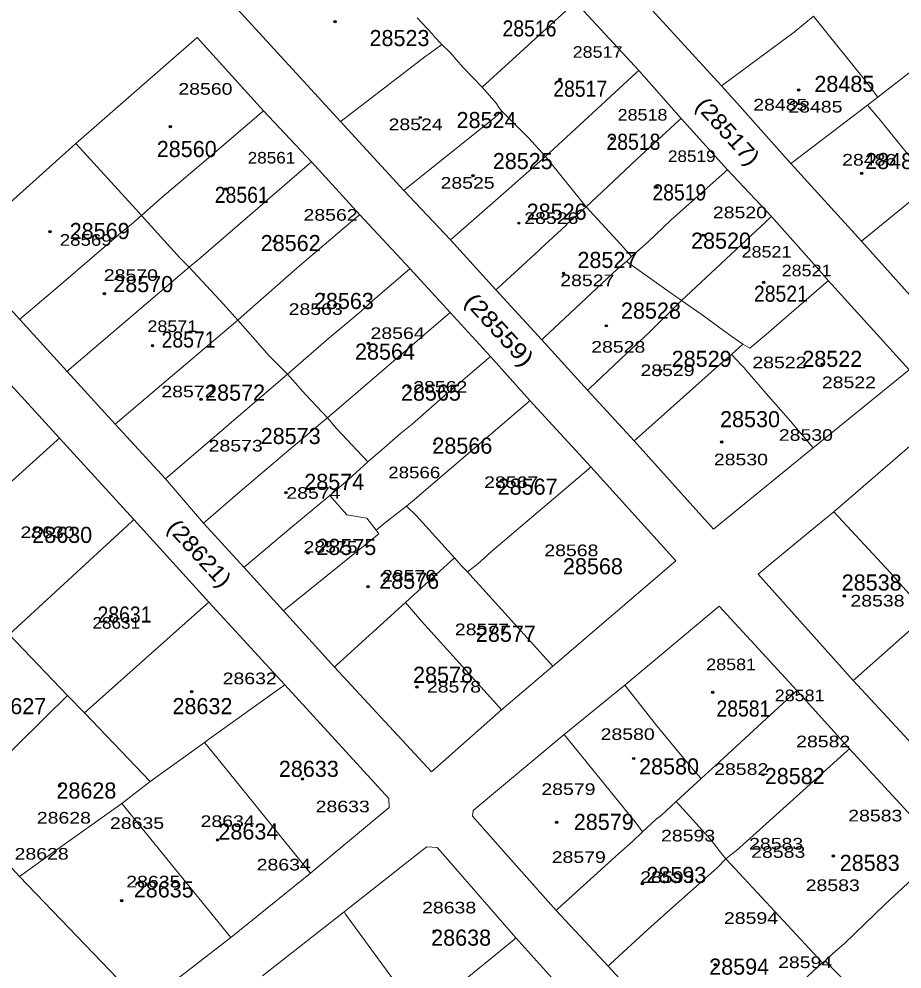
# Model space of a CAD drawing. Extents: x 650553 to 652508, y 239277 to 241647.
# Drawn here: x 651208.2 to 651405.4, y 240724.2 to 240936.5 of the extents above; entities that cross this region are included whole.
import ezdxf

# ---------------------------------------------------------------- set-up
doc = ezdxf.new("R2010")
doc.units = 0
doc.header["$PDMODE"] = 32
doc.header["$PDSIZE"] = 0.5
for name, color, linetype in [('19', 7, 'Continuous'), ('20', 7, 'Continuous'), ('6', 7, 'Continuous')]:
    doc.layers.add(name, color=color, linetype=linetype)
doc.layers.add('3', color=7, linetype='Continuous', lineweight=13)
doc.layers.add('5', color=7, linetype='Continuous', lineweight=13)

msp = doc.modelspace()

# ---------------------------------------------------------------- linework, layer by layer
at = {"layer": '3'}
msp.add_line((651343.46, 240787.65), (651329.9, 240776.61), dxfattribs=at)
for points in [[(651277, 240958.16), (651298.11, 240977.12), (651318.05, 240955.47), (651332.44, 240940.26), (651346.55, 240924.99), (651356.03, 240914.24), (651366.39, 240902.79)], [(651380.56, 240904.16), (651375, 240910.37), (651369.11, 240916.96), (651365.03, 240921.5), (651349.46, 240938.51), (651334.15, 240954.49), (651318.32, 240971.34)], [(651279.96, 240913.54), (651256.05, 240939.64), (651277, 240958.16)], [(651220.87, 240908.63), (651247.95, 240932.31), (651262.76, 240915.94), (651273.46, 240904.58), (651284.26, 240892.74), (651295.51, 240880.67), (651304.42, 240870.91), (651313.42, 240861.04), (651322.27, 240851.23), (651335.9, 240836.4)], [(651385.53, 240840.68), (651375, 240832.09), (651363.23, 240822.48), (651345.55, 240842.23), (651335.12, 240853.52), (651324.91, 240864.81), (651314.68, 240875.96), (651304.55, 240887.13), (651294.1, 240898.18), (651279.96, 240913.54)], [(651208.31, 240869.33), (651194.27, 240884.81), (651220.87, 240908.63)], [(651366.39, 240902.79), (651375, 240893.59), (651376.18, 240892.33)], [(651430.38, 240877.39), (651415.54, 240865.35), (651396.3, 240886.8), (651380.56, 240904.16)], [(651376.18, 240892.33), (651386.915, 240880.255), (651388.92, 240878)], [(651165.74, 240859.56), (651185.75, 240877.17), (651202.38, 240859), (651217.18, 240842.81), (651233.79, 240824.62), (651250.56, 240806.18), (651267.52, 240787.73)], [(651388.92, 240878), (651406.98, 240858.1), (651385.53, 240840.68)], [(651315.92, 240782.11), (651300.27, 240768.31), (651278.58, 240791.67), (651267.23, 240804.28), (651258.4, 240813.97), (651249.36, 240823.83), (651240.86, 240833.76), (651229.66, 240845.97), (651218.88, 240857.7), (651208.31, 240869.33)], [(651390.1, 240826.37), (651415.79, 240848.55), (651436.19, 240825.84)], [(651335.9, 240836.4), (651354.84, 240815.44), (651327.38, 240791.89), (651315.92, 240782.11)], [(651375, 240813.9), (651386.148, 240823.106), (651390.1, 240826.37)], [(651375, 240813.9), (651373.2, 240812.42), (651375, 240810.41)], [(651208.28, 240744.9), (651203.48, 240750), (651193.67, 240760.43), (651177.86, 240776.79), (651162.01, 240793.16), (651146.4, 240809.27)], [(651375, 240810.41), (651394.45, 240788.7), (651405.88, 240776.28), (651417.31, 240763.69), (651428.702, 240751.214)], [(651375, 240793.89), (651364.54, 240805.26), (651343.46, 240787.65)], [(651375, 240793.89), (651381.88, 240786.41), (651393.61, 240773.4), (651414.55, 240750.7), (651415.19, 240750)], [(651267.52, 240787.73), (651290.76, 240762.29), (651290.81, 240760.29), (651278.45, 240750), (651273.22, 240745.65), (651255.48, 240731.26)], [(651329.9, 240776.61), (651309.57, 240759.62), (651309.42, 240758.34), (651316.83, 240750)], [(651262.55, 240722.73), (651280.74, 240736.96), (651297.28, 240750)], [(651302.75, 240750), (651301.54, 240751.39), (651299.25, 240751.55), (651297.28, 240750)], [(651302.75, 240750), (651319.13, 240731.15), (651331.81, 240717.05), (651347.16, 240700.26), (651362.6, 240683.5), (651375, 240670.03)], [(651369.97, 240691.81), (651368.88, 240693.01), (651361.16, 240701.58), (651339.76, 240724.88), (651328.09, 240737.32), (651316.83, 240750)], [(651255.48, 240731.26), (651238.03, 240717.81), (651233.93, 240718.13), (651208.28, 240744.9)]]:
    msp.add_lwpolyline(points, dxfattribs=at)
at = {"layer": '5'}
for p, q in [((651325.71, 240905.76), (651313.89, 240895.31)), ((651396.3, 240886.8), (651412.1, 240899.78)), ((651356.14, 240873.55), (651348.86, 240866.39)), ((651257.05, 240869.2), (651238.03, 240853.13)), ((651277.58, 240830.02), (651281.34, 240825.68)), ((651402.77, 240812.7), (651390.1, 240826.37)), ((651219, 240785.29), (651205.99, 240798.98)), ((651237.46, 240766.15), (651222.76, 240781.42)), ((651249.59, 240774.83), (651252.315, 240771.465)), ((651255.48, 240731.26), (651240.23, 240750)), ((651365.99, 240748.81), (651365.07, 240750)), ((651365.99, 240748.81), (651375, 240739.13)), ((651387.627, 240725.567), (651375, 240739.13))]:
    msp.add_line(p, q, dxfattribs=at)
for points in [[(651397.68, 240917.22), (651399.98, 240918.99), (651432.63, 240944.47)], [(651311.58, 240921.24), (651331.94, 240939.804), (651332.44, 240940.26)], [(651297.06, 240936.72), (651300.53, 240933.07), (651300.98, 240932.48), (651302.55, 240930.74), (651299.76, 240928.68), (651299.1, 240928.23)], [(651399.98, 240918.99), (651396.6, 240923.39), (651389.13, 240932.6), (651385.61, 240937.08), (651381.24, 240933.55), (651375, 240928.91)], [(651302.55, 240930.74), (651304.43, 240928.96), (651307.24, 240925.67), (651311.58, 240921.24)], [(651299.1, 240928.23), (651280.46, 240913.924), (651279.96, 240913.54)], [(651365.03, 240921.5), (651365.53, 240921.872), (651375, 240928.91)], [(651332.39, 240911.85), (651346.05, 240924.526), (651346.55, 240924.99)], [(651311.58, 240921.24), (651314.78, 240917.57), (651315.28, 240916.72), (651315.97, 240915.84), (651314.43, 240914.49)], [(651397.68, 240917.22), (651381.06, 240904.541), (651380.56, 240904.16)], [(651430.38, 240877.39), (651429.968, 240877.89), (651422.71, 240886.7), (651415.97, 240895.15), (651412.1, 240899.78), (651408.2, 240904.34), (651401.46, 240912.71), (651400.99, 240913.24), (651397.68, 240917.22)], [(651251.39, 240906.19), (651262.26, 240915.511), (651262.76, 240915.94)], [(651315.97, 240915.84), (651321.95, 240909.9), (651325.71, 240905.76), (651332.39, 240911.85)], [(651314.43, 240914.49), (651294.6, 240898.581), (651294.1, 240898.18)], [(651346.1, 240905.15), (651355.53, 240913.782), (651356.03, 240914.24)], [(651220.87, 240908.63), (651234.21, 240894), (651235.5, 240892.55), (651240.14, 240896.69), (651251.39, 240906.19)], [(651248.75, 240883.19), (651272.96, 240904.147), (651273.46, 240904.58)], [(651325.71, 240905.76), (651334.8, 240894.52), (651340.84, 240900.2), (651346.1, 240905.15)], [(651353.74, 240891.54), (651365.89, 240902.345), (651366.39, 240902.79)], [(651313.89, 240895.31), (651305.05, 240887.568), (651304.55, 240887.13)], [(651334.8, 240894.52), (651330.55, 240890.67), (651330.25, 240890.32), (651324.72, 240885.23), (651324.28, 240884.77)], [(651334.8, 240894.52), (651342.56, 240886.06), (651344.92, 240883.42), (651348.66, 240886.7), (651353.74, 240891.54)], [(651235.5, 240892.55), (651233.21, 240890.57), (651231.41, 240889.12), (651217.57, 240877.22)], [(651235.5, 240892.55), (651244.06, 240883.12), (651246.19, 240880.99), (651248.75, 240883.19)], [(651271.81, 240882.22), (651283.76, 240892.318), (651284.26, 240892.74)], [(651376.18, 240892.33), (651375.68, 240891.86), (651375, 240891.22)], [(651343.8, 240882.32), (651352.31, 240876.24), (651356.14, 240873.55), (651357.08, 240874.5), (651375, 240891.22)], [(651324.28, 240884.77), (651315.18, 240876.419), (651314.68, 240875.96)], [(651344.92, 240883.42), (651343.8, 240882.32), (651341.75, 240880.57)], [(651246.19, 240880.99), (651253.84, 240872.72), (651257.05, 240869.2), (651259.08, 240871.04), (651270.8, 240881.3), (651271.81, 240882.22)], [(651246.19, 240880.99), (651219.38, 240858.126), (651218.88, 240857.7)], [(651287.09, 240873.47), (651295.01, 240880.242), (651295.51, 240880.67)], [(651341.75, 240880.57), (651325.41, 240865.278), (651324.91, 240864.81)], [(651217.57, 240877.22), (651208.81, 240869.756), (651208.31, 240869.33)], [(651388.92, 240878), (651388.42, 240877.567), (651376.226, 240867.009), (651375, 240865.98)], [(651257.05, 240869.2), (651260.92, 240864.79), (651263.92, 240861.32), (651268.1, 240857.11), (651269.87, 240858.68), (651277.32, 240865.19), (651281.79, 240868.92), (651284.54, 240871.22), (651287.09, 240873.47)], [(651356.14, 240873.55), (651360.72, 240870.34), (651366.62, 240866.09), (651369.84, 240863.85), (651371.38, 240862.94), (651375, 240865.98)], [(651277.05, 240847.33), (651303.92, 240870.479), (651304.42, 240870.91)], [(651345.01, 240862.86), (651346.53, 240864.21), (651348.86, 240866.39)], [(651345.01, 240862.86), (651335.62, 240853.992), (651335.12, 240853.52)], [(651369.84, 240863.85), (651367.26, 240861.49), (651364.8, 240859.39)], [(651306.8, 240855.38), (651312.92, 240860.613), (651313.42, 240861.04)], [(651367.26, 240861.49), (651369.56, 240859.06), (651370.01, 240858.6)], [(651364.8, 240859.39), (651346.05, 240842.676), (651345.55, 240842.23)], [(651370.01, 240858.6), (651375, 240852.77), (651379.961, 240847.191), (651385.53, 240840.68)], [(651268.1, 240857.11), (651241.36, 240834.189), (651240.86, 240833.76)], [(651268.1, 240857.11), (651272.11, 240852.59), (651277.05, 240847.33)], [(651277.05, 240847.33), (651279, 240845.08), (651286.06, 240837.5), (651290.27, 240841.21), (651290.98, 240841.77), (651293.39, 240843.88), (651295.96, 240845.98), (651302.23, 240851.45), (651306.8, 240855.38)], [(651238.03, 240853.13), (651230.16, 240846.398), (651229.66, 240845.97)], [(651296.47, 240829.13), (651321.77, 240850.802), (651322.27, 240851.23)], [(651277.05, 240847.33), (651275.84, 240846.37), (651267.49, 240839.43), (651264.94, 240837.16), (651262.53, 240835.14), (651257.54, 240830.88)], [(651188.61, 240817.03), (651216.68, 240842.359), (651217.18, 240842.81)], [(651286.06, 240837.5), (651281.64, 240833.54), (651277.58, 240830.02), (651268.42, 240822.41)], [(651313.77, 240817.56), (651335.4, 240835.974), (651335.9, 240836.4)], [(651257.54, 240830.88), (651249.86, 240824.261), (651249.36, 240823.83)], [(651287.93, 240822.23), (651290.05, 240824.05), (651294.68, 240827.64), (651296.47, 240829.13)], [(651294.68, 240827.64), (651296.93, 240825.46), (651305.39, 240816.07), (651299.73, 240810.97), (651294.44, 240806.14)], [(651205.99, 240798.98), (651233.29, 240824.159), (651233.79, 240824.62)], [(651281.34, 240825.68), (651285.87, 240824.95), (651287.93, 240822.23)], [(651268.42, 240822.41), (651258.9, 240814.391), (651258.4, 240813.97)], [(651287.93, 240822.23), (651288.48, 240821.42), (651267.73, 240804.683), (651267.23, 240804.28)], [(651308.35, 240812.97), (651309.86, 240814.18), (651311.24, 240815.3), (651313.77, 240817.56)], [(651305.39, 240816.07), (651306.92, 240814.39), (651308.35, 240812.97), (651308.82, 240812.36), (651327.38, 240791.89)], [(651411.14, 240803.44), (651404.847, 240810.382), (651402.77, 240812.7)], [(651222.76, 240781.42), (651250.06, 240805.735), (651250.56, 240806.18)], [(651294.44, 240806.14), (651279.08, 240792.126), (651278.58, 240791.67)], [(651294.44, 240806.14), (651298.08, 240801.96), (651307.18, 240791.83)], [(651411.14, 240803.44), (651394.95, 240789.142), (651394.45, 240788.7)], [(651307.18, 240791.83), (651315.47, 240782.61), (651315.92, 240782.11)], [(651251.04, 240775.92), (651267.02, 240787.372), (651267.52, 240787.73)], [(651360.5, 240766.77), (651359.17, 240768.28), (651356.27, 240771.7), (651350.61, 240778.55), (651343.46, 240787.65)], [(651381.88, 240786.41), (651381.38, 240785.95), (651375, 240780.08)], [(651222.76, 240781.42), (651219, 240785.29), (651213.96, 240780.44)], [(651213.96, 240780.44), (651194.17, 240760.923), (651193.67, 240760.43)], [(651354.91, 240761.67), (651360.5, 240766.77), (651364.6, 240770.51), (651375, 240780.08)], [(651231.11, 240761.21), (651237.46, 240766.15), (651247.74, 240773.51), (651249.59, 240774.83), (651251.04, 240775.92)], [(651347.43, 240754.87), (651345.73, 240757.12), (651345.35, 240757.66), (651329.9, 240776.61)], [(651393.61, 240773.4), (651393.11, 240772.949), (651375, 240756.63)], [(651252.315, 240771.465), (651272.815, 240746.15), (651273.22, 240745.65)], [(651215.42, 240750), (651231.11, 240761.21), (651240.23, 240750)], [(651365.07, 240750), (651362.74, 240753.03), (651358.65, 240757.58), (651354.91, 240761.67), (651351.59, 240758.54), (651350.49, 240757.68), (651347.43, 240754.87), (651345.14, 240752.71), (651342.13, 240750)], [(651375, 240756.63), (651368.43, 240750.71), (651367.52, 240750)], [(651208.28, 240744.9), (651208.78, 240745.257), (651215.42, 240750)], [(651328.09, 240737.32), (651328.59, 240737.772), (651342.13, 240750)], [(651339.76, 240724.88), (651340.26, 240725.341), (651348.63, 240733.06), (651353.49, 240737.43), (651364.09, 240746.84), (651365.99, 240748.81), (651367.52, 240750)], [(651397.508, 240716.45), (651396.065, 240717.916), (651388.221, 240726.041), (651389.808, 240727.583), (651392.535, 240729.948), (651401.538, 240738.647), (651413.8, 240750)], [(651280.74, 240736.96), (651281.106, 240736.46), (651295.91, 240716.23), (651297.02, 240714.77)], [(651297.71, 240713.68), (651318.63, 240730.742), (651319.13, 240731.15)], [(651388.221, 240726.041), (651387.627, 240725.567), (651385.693, 240723.853), (651375.231, 240713.996)]]:
    msp.add_lwpolyline(points, dxfattribs=at)
at = {"layer": '6'}
for p in [(651278.705, 240935.85), (651328.969, 240923.01), (651382.274, 240920.62), (651297.775, 240914.46), (651241.941, 240912.43), (651340.611, 240909.755), (651309.547, 240901.485), (651396.351, 240902.01), (651254.319, 240898.465), (651350.66, 240898.83), (651319.784, 240890.86), (651215.087, 240888.98), (651360.967, 240888.17), (651265.18, 240886.89), (651329.75, 240879.665), (651374.469, 240877.635), (651227.212, 240875.125), (651276.155, 240874.925), (651339.324, 240867.92), (651286.179, 240864), (651237.969, 240863.48), (651351.432, 240857.89), (651387.575, 240859.34), (651295.232, 240854.205), (651248.817, 240851.48), (651300.939, 240841.635), (651365.092, 240841.985), (651258.714, 240840.47), (651315.393, 240832.1), (651267.79, 240830.65), (651211.322, 240820.895), (651272.681, 240817.15), (651331.573, 240814.145), (651286.092, 240809.655), (651392.502, 240807.535), (651228.691, 240803.02), (651310.755, 240799.09), (651246.712, 240786.165), (651297.014, 240787.225), (651363.098, 240786.015), (651345.452, 240771.26), (651271.461, 240766.69), (651374.303, 240767.61), (651217.252, 240765.095), (651328.244, 240756.965), (651252.492, 240753.045), (651390.048, 240749.483), (651347.379, 240743.275), (651231.105, 240739.51), (651300.888, 240732.615), (651363.654, 240725.195)]:
    msp.add_point(p, dxfattribs=at)

# ---------------------------------------------------------------- texts
at = {"layer": '19', "width": 0.9}
for s, p in [('28516', (651316.131, 240932.562)), ('28517', (651327.47, 240919.092)), ('28518', (651339.349, 240907.237)), ('28561', (651251.876, 240895.383)), ('28519', (651349.609, 240895.922)), ('28521', (651372.287, 240873.291)), ('28571', (651239.998, 240863.054)), ('28631', (651225.688, 240801.629)), ('28581', (651363.918, 240780.615))]:
    msp.add_text(s, height=3.6, dxfattribs=at).set_placement(p)
at = {"layer": '19'}
for s, p in [('28523', (651286.433, 240930.407)), ('28485', (651385.787, 240920.171)), ('28524', (651305.871, 240912.087)), ('28560', (651238.916, 240905.621)), ('28525', (651313.971, 240902.927)), ('28486', (651397.127, 240902.928)), ('28526', (651321.532, 240891.612)), ('28569', (651219.478, 240887.301)), ('28562', (651262.135, 240884.607)), ('28520', (651358.247, 240885.146)), ('28527', (651332.871, 240880.835)), ('28570', (651229.197, 240875.447)), ('28563', (651274.014, 240871.675)), ('28528', (651342.589, 240869.52)), ('28564', (651283.193, 240860.359)), ('28529', (651353.93, 240858.743)), ('28522', (651383.087, 240858.743)), ('28572', (651249.717, 240851.199)), ('28565', (651293.453, 240851.199)), ('28530', (651364.728, 240845.273)), ('28573', (651262.136, 240841.501)), ('28566', (651300.473, 240839.345)), ('28574', (651271.855, 240831.263)), ('28567', (651315.052, 240830.185)), ('28630', (651211.108, 240819.41)), ('28575', (651274.555, 240816.715)), ('28568', (651329.631, 240812.404)), ('28576', (651288.594, 240809.171)), ('28538', (651391.897, 240808.768)), ('28577', (651310.193, 240797.317)), ('28578', (651296.154, 240788.157)), ('28627', (651200.849, 240781.154)), ('28632', (651242.427, 240781.154)), ('28633', (651266.185, 240767.144)), ('28580', (651346.638, 240767.683)), ('28582', (651374.717, 240765.528)), ('28628', (651216.508, 240762.295)), ('28579', (651332.06, 240755.29)), ('28634', (651252.685, 240753.135)), ('28583', (651391.456, 240746.13)), ('28593', (651348.259, 240743.436)), ('28635', (651233.787, 240740.203)), ('28638', (651300.202, 240729.426)), ('28594', (651362.297, 240722.96))]:
    msp.add_text(s, height=3.6, dxfattribs=at).set_placement(p)
for s, rotation, width, p in [('(28517)', 312.139, 1.1, (651358.996, 240916.925)), ('(28559)', 312.36, 1.2, (651307.376, 240873.2)), ('(28621)', 312.285, 1.1, (651240.993, 240822.646))]:
    msp.add_text(s, height=3.6, rotation=rotation, dxfattribs=dict(at, width=width)).set_placement(p)
at = {"layer": '20'}
for s, width, p in [('28517', 1.15, (651331.807, 240927.792)), ('28560', 1.25, (651243.742, 240919.548)), ('28485', 1.25, (651372.141, 240916.021)), ('28485', 1.25, (651379.979, 240915.561)), ('28518', 1.15, (651341.845, 240913.767)), ('28524', 1.25, (651290.691, 240911.631)), ('28561', 1.1, (651259.223, 240904.172)), ('28519', 1.1, (651353.083, 240904.522)), ('28486', 1.25, (651391.988, 240903.715)), ('28525', 1.25, (651302.293, 240898.549)), ('28562', 1.25, (651271.69, 240891.401)), ('28520', 1.25, (651363.121, 240891.954)), ('28526', 1.25, (651320.998, 240890.677)), ('28569', 1.2, (651217.244, 240885.801)), ('28521', 1.15, (651369.54, 240883.151)), ('28521', 1.15, (651378.486, 240878.974)), ('28570', 1.25, (651227.1, 240877.948)), ('28527', 1.25, (651329.033, 240876.774)), ('28563', 1.25, (651268.371, 240870.35)), ('28571', 1.15, (651236.836, 240866.531)), ('28564', 1.25, (651286.657, 240864.979)), ('28528', 1.25, (651335.944, 240861.919)), ('28522', 1.25, (651371.938, 240858.428)), ('28529', 1.25, (651346.939, 240856.697)), ('28562', 1.25, (651296.192, 240852.969)), ('28522', 1.25, (651387.464, 240853.988)), ('28572', 1.25, (651239.94, 240851.947)), ('28530', 1.25, (651377.851, 240842.226)), ('28573', 1.25, (651250.506, 240839.837)), ('28530', 1.25, (651363.34, 240836.753)), ('28566', 1.2, (651290.623, 240833.859)), ('28567', 1.25, (651312.032, 240831.681)), ('28574', 1.25, (651267.861, 240829.278)), ('28630', 1.25, (651208.482, 240820.498)), ('28575', 1.25, (651271.691, 240817.235)), ('28568', 1.25, (651325.469, 240816.455)), ('28576', 1.25, (651289.228, 240810.768)), ('28538', 1.25, (651393.838, 240805.202)), ('28631', 1.1, (651224.567, 240800.242)), ('28577', 1.25, (651305.5, 240798.789)), ('28581', 1.15, (651361.635, 240790.981)), ('28632', 1.25, (651253.631, 240787.843)), ('28578', 1.25, (651299.248, 240785.987)), ('28581', 1.15, (651376.939, 240784.051)), ('28580', 1.25, (651338.047, 240775.392)), ('28582', 1.25, (651381.724, 240773.755)), ('28582', 1.25, (651363.41, 240767.583)), ('28579', 1.25, (651324.816, 240763.107)), ('28633', 1.25, (651274.402, 240759.231)), ('28628', 1.25, (651212.128, 240756.709)), ('28635', 1.25, (651228.47, 240755.514)), ('28634', 1.25, (651248.698, 240755.95)), ('28583', 1.25, (651393.352, 240757.191)), ('28593', 1.25, (651351.542, 240752.717)), ('28583', 1.25, (651371.207, 240750.913)), ('28583', 1.25, (651371.676, 240749.06)), ('28628', 1.25, (651207.16, 240748.654)), ('28579', 1.25, (651327.124, 240747.926)), ('28634', 1.25, (651261.228, 240746.236)), ('28593', 1.25, (651346.893, 240743.451)), ('28635', 1.25, (651232.104, 240742.442)), ('28583', 1.25, (651383.846, 240741.629)), ('28638', 1.25, (651298.172, 240736.641)), ('28594', 1.25, (651365.598, 240734.299)), ('28594', 1.25, (651377.688, 240724.426))]:
    msp.add_text(s, height=2.6, dxfattribs=dict(at, width=width)).set_placement(p)

doc.saveas('drawing.dxf')
